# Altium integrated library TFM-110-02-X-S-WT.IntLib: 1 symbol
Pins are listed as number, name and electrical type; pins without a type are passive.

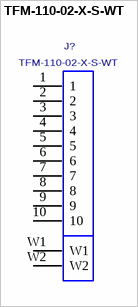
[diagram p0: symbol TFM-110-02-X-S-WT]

## TFM-110-02-X-S-WT
designator J?
.050 C.L. SINGLE ROW SHROUDED TERMINAL STRIP, SURFACE MOUNT.; MANUFACTURER: SAMTEC
footprint TFM-110-02-X-S-WT
pins: 1, 2, 3, 4, 5, 6, 7, 8, 9, 10, W1, W2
